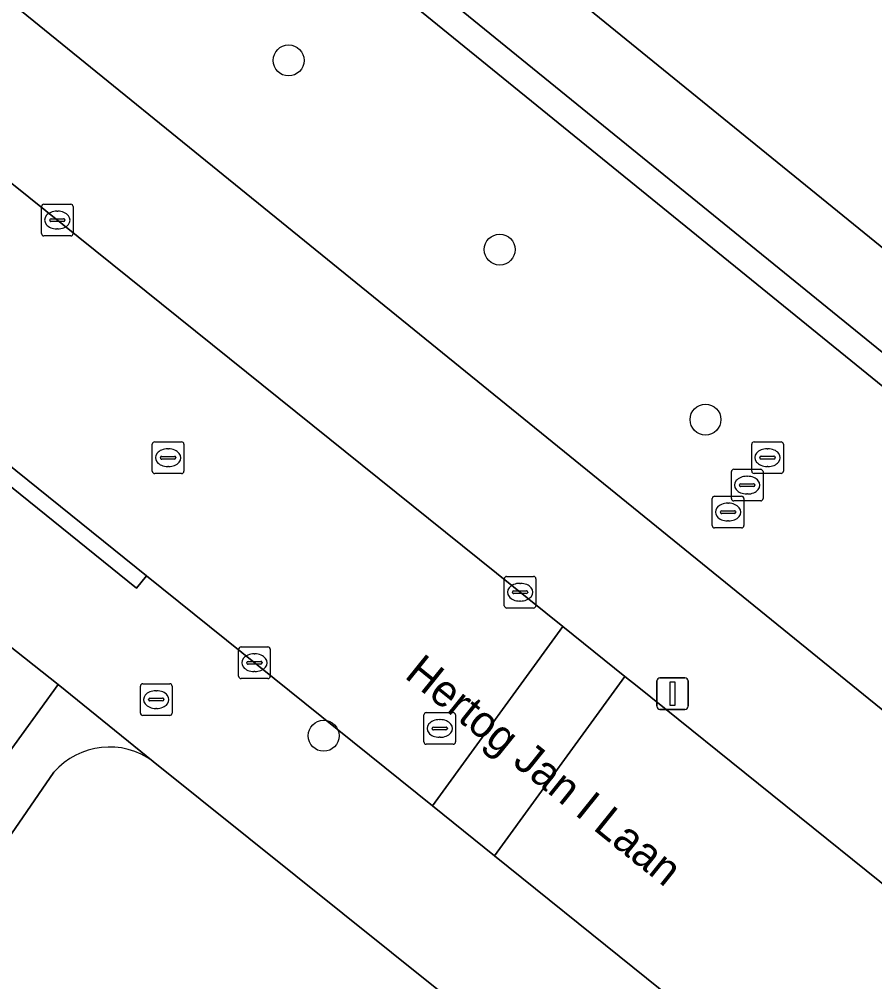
# Model space of a CAD drawing. Extents: x 159674 to 160531, y 382172 to 382904.
# Drawn here: x 160312.02 to 160339.08, y 382680.52 to 382710.95 of the extents above; entities that cross this region are included whole.
import ezdxf

# ---------------------------------------------------------------- set-up
doc = ezdxf.new("R2010")
doc.units = 0
for name, color, linetype in [('IMGEO_Boom', 7, 'Continuous'), ('IMGEO_Brandkraan', 7, 'Continuous'), ('IMGEO_Erf', 7, 'Continuous'), ('IMGEO_Groenvoorziening', 7, 'Continuous'), ('IMGEO_Haag', 7, 'Continuous'), ('IMGEO_Kolk', 7, 'Continuous'), ('IMGEO_Lichtmast', 7, 'Continuous'), ('IMGEO_Openbare_ruimte_label', 7, 'Continuous'), ('IMGEO_Pand', 7, 'Continuous'), ('IMGEO_Rijbaan_lokaal_open', 7, 'Continuous'), ('IMGEO_Rioolput', 7, 'Continuous'), ('IMGEO_Voetpad_open', 7, 'Continuous')]:
    doc.layers.add(name, color=color, linetype=linetype)

msp = doc.modelspace()

# ---------------------------------------------------------------- linework, layer by layer
at = {"layer": 'IMGEO_Boom'}
for centre in [(160320.54, 382709.645), (160327.217, 382703.665), (160333.725, 382698.29), (160321.648, 382688.295)]:
    msp.add_circle(centre, 0.489, dxfattribs=at)
at = {"layer": 'IMGEO_Brandkraan'}
for p, q in [((160315.853, 382689.013), (160315.853, 382689.865)), ((160315.928, 382689.939), (160316.78, 382689.939)), ((160316.341, 382689.719), (160316.366, 382689.719)), ((160316.854, 382689.865), (160316.854, 382689.013)), ((160316.112, 382689.433), (160316.112, 382689.445)), ((160316.155, 382689.482), (160316.553, 382689.482)), ((160316.596, 382689.445), (160316.596, 382689.433)), ((160316.55, 382689.396), (160316.152, 382689.396)), ((160316.364, 382689.159), (160316.339, 382689.159)), ((160316.78, 382688.939), (160315.928, 382688.939))]:
    msp.add_line(p, q, dxfattribs=at)
for points in [[(160315.853, 382689.013), (160315.853, 382689.865)], [(160315.928, 382689.939), (160316.78, 382689.939)], [(160316.854, 382689.865), (160316.854, 382689.013)], [(160316.78, 382688.939), (160315.928, 382688.939)]]:
    msp.add_lwpolyline(points, dxfattribs=at)
for centre, radius, start, end in [((160315.93, 382689.863), 0.0765, 91.552, 178.448), ((160315.93, 382689.863), 0.0765, 91.552, 178.448), ((160316.778, 382689.863), 0.0765, 1.552, 88.448), ((160316.778, 382689.863), 0.0765, 1.552, 88.448), ((160316.152, 382689.442), 0.0403, 85.8775, 175.7526), ((160316.149, 382689.432), 0.0366, 178.938, 274.7102), ((160316.553, 382689.439), 0.043, 264.8664, 352.4533), ((160316.557, 382689.444), 0.0386, 1.7309, 96.639), ((160315.93, 382689.015), 0.0765, 181.552, 268.448), ((160315.93, 382689.015), 0.0765, 181.552, 268.448), ((160316.778, 382689.015), 0.0765, 271.552, 358.448), ((160316.778, 382689.015), 0.0765, 271.552, 358.448)]:
    msp.add_arc(centre, radius, start, end, dxfattribs=at)
for centre, major_axis, ratio, start_param, end_param in [((160316.34, 382689.439), (-0.387, 0.002), 0.722429, 4.712389, 7.853982), ((160316.365, 382689.439), (-0.39, 0.002), 0.717154, 1.570796, 4.712389)]:
    msp.add_ellipse(centre, major_axis=major_axis, ratio=ratio, start_param=start_param, end_param=end_param, dxfattribs=at)
at = {"layer": 'IMGEO_Erf'}
for points in [[(160332.815, 382674.214), (160316.257, 382687.487)], [(160313.115, 382687.143), (160310.913, 382683.952), (160308.167, 382680.148), (160311.466, 382677.75), (160310.092, 382675.86), (160308.689, 382673.931), (160305.386, 382676.323), (160303.294, 382673.468), (160307.737, 382670.249), (160304.18, 382665.339), (160303.078, 382666.137), (160301.672, 382664.196), (160298.315, 382666.628), (160294.169, 382660.875)]]:
    msp.add_lwpolyline(points, dxfattribs=at)
msp.add_arc((160314.874, 382685.601), 2.339, 53.7429, 138.7534, dxfattribs=at)
at = {"layer": 'IMGEO_Groenvoorziening'}
msp.add_lwpolyline([(160284.89, 382733.272), (160346.941, 382682.927), (160357.009, 382674.758), (160362, 382680.937), (160317.229, 382717.291), (160317.757, 382717.941), (160311.605, 382722.938), (160333.51, 382750), (160355.476, 382777.138), (160357.031, 382776.089), (160357.342, 382775.837), (160360.793, 382780.087), (160357.866, 382782.856), (160305.531, 382750), (160285.03, 382737.24)], dxfattribs=at)
msp.add_lwpolyline([(160317.229, 382717.291), (160362, 382680.937), (160377.094, 382699.627), (160376.864, 382699.817), (160375.385, 382701.033), (160360.708, 382683.056), (160317.757, 382717.941)], close=True, dxfattribs=at)
at = {"layer": 'IMGEO_Haag'}
msp.add_lwpolyline([(160317.229, 382717.291), (160362, 382680.937), (160377.094, 382699.627), (160376.864, 382699.817), (160375.385, 382701.033), (160360.708, 382683.056), (160317.757, 382717.941)], close=True, dxfattribs=at)
at = {"layer": 'IMGEO_Kolk'}
for p, q in [((160312.724, 382704.172), (160312.724, 382705.024)), ((160312.799, 382705.098), (160313.651, 382705.098)), ((160313.725, 382705.024), (160313.725, 382704.172)), ((160313.026, 382704.641), (160313.424, 382704.641)), ((160313.212, 382704.878), (160313.237, 382704.878)), ((160312.983, 382704.592), (160312.983, 382704.604)), ((160313.421, 382704.555), (160313.023, 382704.555)), ((160313.235, 382704.318), (160313.21, 382704.318)), ((160313.467, 382704.604), (160313.467, 382704.592)), ((160313.651, 382704.098), (160312.799, 382704.098)), ((160327.361, 382692.408), (160327.361, 382693.26)), ((160327.436, 382693.334), (160328.288, 382693.334)), ((160327.849, 382693.114), (160327.874, 382693.114)), ((160328.362, 382693.26), (160328.362, 382692.408)), ((160327.62, 382692.828), (160327.62, 382692.84)), ((160328.058, 382692.791), (160327.66, 382692.791)), ((160327.663, 382692.877), (160328.061, 382692.877)), ((160328.104, 382692.84), (160328.104, 382692.828)), ((160327.872, 382692.554), (160327.847, 382692.554)), ((160328.288, 382692.334), (160327.436, 382692.334)), ((160318.959, 382690.178), (160318.959, 382691.03)), ((160319.034, 382691.104), (160319.886, 382691.104)), ((160319.96, 382691.03), (160319.96, 382690.178)), ((160319.261, 382690.647), (160319.659, 382690.647)), ((160319.447, 382690.884), (160319.472, 382690.884)), ((160319.218, 382690.598), (160319.218, 382690.61)), ((160319.656, 382690.561), (160319.258, 382690.561)), ((160319.47, 382690.324), (160319.445, 382690.324)), ((160319.702, 382690.61), (160319.702, 382690.598)), ((160319.886, 382690.104), (160319.034, 382690.104))]:
    msp.add_line(p, q, dxfattribs=at)
for points in [[(160312.724, 382704.172), (160312.724, 382705.024)], [(160312.799, 382705.098), (160313.651, 382705.098)], [(160313.725, 382705.024), (160313.725, 382704.172)], [(160313.651, 382704.098), (160312.799, 382704.098)], [(160327.361, 382692.408), (160327.361, 382693.26)], [(160327.436, 382693.334), (160328.288, 382693.334)], [(160328.362, 382693.26), (160328.362, 382692.408)], [(160328.288, 382692.334), (160327.436, 382692.334)], [(160318.959, 382690.178), (160318.959, 382691.03)], [(160319.034, 382691.104), (160319.886, 382691.104)], [(160319.96, 382691.03), (160319.96, 382690.178)], [(160319.886, 382690.104), (160319.034, 382690.104)]]:
    msp.add_lwpolyline(points, dxfattribs=at)
for centre, radius, start, end in [((160312.801, 382705.022), 0.0765, 91.552, 178.448), ((160312.801, 382705.022), 0.0765, 91.552, 178.448), ((160313.649, 382705.022), 0.0765, 1.552, 88.448), ((160313.649, 382705.022), 0.0765, 1.552, 88.448), ((160313.023, 382704.601), 0.0403, 85.8775, 175.7526), ((160313.428, 382704.603), 0.0386, 1.7309, 96.639), ((160313.02, 382704.591), 0.0366, 178.938, 274.7102), ((160313.424, 382704.598), 0.043, 264.8664, 352.4533), ((160312.801, 382704.174), 0.0765, 181.552, 268.448), ((160312.801, 382704.174), 0.0765, 181.552, 268.448), ((160313.649, 382704.174), 0.0765, 271.552, 358.448), ((160313.649, 382704.174), 0.0765, 271.552, 358.448), ((160327.438, 382693.258), 0.0765, 91.552, 178.448), ((160327.438, 382693.258), 0.0765, 91.552, 178.448), ((160328.286, 382693.258), 0.0765, 1.552, 88.448), ((160328.286, 382693.258), 0.0765, 1.552, 88.448), ((160327.66, 382692.837), 0.0403, 85.8775, 175.7526), ((160327.657, 382692.827), 0.0366, 178.938, 274.7102), ((160328.061, 382692.834), 0.043, 264.8664, 352.4533), ((160328.065, 382692.839), 0.0386, 1.7309, 96.639), ((160327.438, 382692.41), 0.0765, 181.552, 268.448), ((160327.438, 382692.41), 0.0765, 181.552, 268.448), ((160328.286, 382692.41), 0.0765, 271.552, 358.448), ((160328.286, 382692.41), 0.0765, 271.552, 358.448), ((160319.036, 382691.028), 0.0765, 91.552, 178.448), ((160319.036, 382691.028), 0.0765, 91.552, 178.448), ((160319.884, 382691.028), 0.0765, 1.552, 88.448), ((160319.884, 382691.028), 0.0765, 1.552, 88.448), ((160319.258, 382690.607), 0.0403, 85.8775, 175.7526), ((160319.663, 382690.609), 0.0386, 1.7309, 96.639), ((160319.255, 382690.597), 0.0366, 178.938, 274.7102), ((160319.659, 382690.604), 0.043, 264.8664, 352.4533), ((160319.036, 382690.18), 0.0765, 181.552, 268.448), ((160319.036, 382690.18), 0.0765, 181.552, 268.448), ((160319.884, 382690.18), 0.0765, 271.552, 358.448), ((160319.884, 382690.18), 0.0765, 271.552, 358.448)]:
    msp.add_arc(centre, radius, start, end, dxfattribs=at)
for centre, major_axis, ratio, start_param, end_param in [((160313.211, 382704.598), (-0.387, 0.002), 0.722429, 4.712389, 7.853982), ((160313.236, 382704.598), (-0.39, 0.002), 0.717154, 1.570796, 4.712389), ((160327.848, 382692.834), (-0.387, 0.002), 0.722429, 4.712389, 7.853982), ((160327.873, 382692.834), (-0.39, 0.002), 0.717154, 1.570796, 4.712389), ((160319.446, 382690.604), (-0.387, 0.002), 0.722429, 4.712389, 7.853982), ((160319.471, 382690.604), (-0.39, 0.002), 0.717154, 1.570796, 4.712389)]:
    msp.add_ellipse(centre, major_axis=major_axis, ratio=ratio, start_param=start_param, end_param=end_param, dxfattribs=at)
at = {"layer": 'IMGEO_Lichtmast'}
for p, q in [((160332.184, 382689.228), (160332.184, 382690.028)), ((160332.184, 382690.028), (160332.184, 382689.228)), ((160332.284, 382690.128), (160333.074, 382690.128)), ((160333.074, 382690.128), (160332.284, 382690.128)), ((160333.174, 382690.028), (160333.174, 382689.228)), ((160333.174, 382689.228), (160333.174, 382690.028)), ((160333.074, 382689.128), (160332.284, 382689.128)), ((160332.284, 382689.128), (160333.074, 382689.128))]:
    msp.add_line(p, q, dxfattribs=at)
msp.add_lwpolyline([(160332.604, 382690.003), (160332.754, 382690.003), (160332.754, 382689.253), (160332.604, 382689.253), (160332.604, 382690.003)], dxfattribs=at)
for centre, start, end in [((160332.284, 382690.028), 90, 180), ((160332.284, 382690.028), 90, 180), ((160333.074, 382690.028), 0, 90), ((160333.074, 382690.028), 360, 90), ((160332.284, 382689.228), 180, 270), ((160332.284, 382689.228), 180, 270), ((160333.074, 382689.228), 270, 0), ((160333.074, 382689.228), 270, 0)]:
    msp.add_arc(centre, 0.1, start, end, dxfattribs=at)
at = {"layer": 'IMGEO_Pand'}
msp.add_lwpolyline([(160360.202, 382686.777), (160373.514, 382703.17), (160373.99, 382702.783), (160379.13, 382709.111), (160381.203, 382707.428), (160385.383, 382712.576), (160383.354, 382714.223), (160388.465, 382720.517), (160387.964, 382720.924), (160401.236, 382737.269), (160363.137, 382768.208), (160322.118, 382717.701)], close=True, dxfattribs=at)
at = {"layer": 'IMGEO_Rijbaan_lokaal_open'}
for points in [[(160329.213, 382691.747), (160292.249, 382721.456), (160287.892, 382716), (160311.584, 382696.94), (160316.045, 382693.352), (160325.09, 382686.076)], [(160331.172, 382690.173), (160329.213, 382691.747), (160325.09, 382686.076), (160327.048, 382684.5)]]:
    msp.add_lwpolyline(points, close=True, dxfattribs=at)
for points in [[(160281.885, 382651.597), (160284.25, 382649.875), (160313.249, 382689.912), (160309.343, 382693.001), (160289.284, 382665.402)], [(160331.562, 382689.859), (160331.172, 382690.173), (160327.048, 382684.5), (160335.801, 382677.459)], [(160336.801, 382669.305), (160336.907, 382669.427), (160344.376, 382679.555), (160331.562, 382689.859)]]:
    msp.add_lwpolyline(points, dxfattribs=at)
at = {"layer": 'IMGEO_Rioolput'}
for p, q in [((160316.229, 382696.66), (160316.229, 382697.512)), ((160316.304, 382697.586), (160317.156, 382697.586)), ((160316.717, 382697.366), (160316.742, 382697.366)), ((160317.23, 382697.512), (160317.23, 382696.66)), ((160335.186, 382696.662), (160335.186, 382697.514)), ((160335.261, 382697.588), (160336.113, 382697.588)), ((160335.674, 382697.368), (160335.699, 382697.368)), ((160336.187, 382697.514), (160336.187, 382696.662)), ((160316.488, 382697.08), (160316.488, 382697.092)), ((160316.926, 382697.043), (160316.528, 382697.043)), ((160316.531, 382697.129), (160316.929, 382697.129)), ((160316.972, 382697.092), (160316.972, 382697.08)), ((160335.445, 382697.082), (160335.445, 382697.094)), ((160335.883, 382697.045), (160335.485, 382697.045)), ((160335.488, 382697.131), (160335.886, 382697.131)), ((160335.929, 382697.094), (160335.929, 382697.082)), ((160316.74, 382696.806), (160316.715, 382696.806)), ((160334.618, 382696.719), (160335.47, 382696.719)), ((160335.697, 382696.808), (160335.672, 382696.808)), ((160317.156, 382696.586), (160316.304, 382696.586)), ((160334.543, 382695.793), (160334.543, 382696.645)), ((160335.031, 382696.499), (160335.056, 382696.499)), ((160336.113, 382696.588), (160335.261, 382696.588)), ((160335.544, 382696.645), (160335.544, 382695.793)), ((160334.802, 382696.213), (160334.802, 382696.225)), ((160335.24, 382696.176), (160334.842, 382696.176)), ((160334.845, 382696.262), (160335.243, 382696.262)), ((160335.286, 382696.225), (160335.286, 382696.213)), ((160333.939, 382694.941), (160333.939, 382695.793)), ((160334.014, 382695.867), (160334.866, 382695.867)), ((160334.94, 382695.793), (160334.94, 382694.941)), ((160335.054, 382695.939), (160335.029, 382695.939)), ((160334.427, 382695.647), (160334.452, 382695.647)), ((160335.47, 382695.719), (160334.618, 382695.719)), ((160334.198, 382695.361), (160334.198, 382695.373)), ((160334.636, 382695.324), (160334.238, 382695.324)), ((160334.241, 382695.41), (160334.639, 382695.41)), ((160334.682, 382695.373), (160334.682, 382695.361)), ((160334.45, 382695.087), (160334.425, 382695.087)), ((160334.866, 382694.867), (160334.014, 382694.867)), ((160324.82, 382688.1), (160324.82, 382688.952)), ((160324.895, 382689.026), (160325.747, 382689.026)), ((160325.308, 382688.806), (160325.333, 382688.806)), ((160325.821, 382688.952), (160325.821, 382688.1)), ((160325.079, 382688.52), (160325.079, 382688.532)), ((160325.122, 382688.569), (160325.52, 382688.569)), ((160325.563, 382688.532), (160325.563, 382688.52)), ((160325.517, 382688.483), (160325.119, 382688.483)), ((160325.331, 382688.246), (160325.306, 382688.246)), ((160325.747, 382688.026), (160324.895, 382688.026))]:
    msp.add_line(p, q, dxfattribs=at)
for points in [[(160316.229, 382696.66), (160316.229, 382697.512)], [(160316.304, 382697.586), (160317.156, 382697.586)], [(160317.23, 382697.512), (160317.23, 382696.66)], [(160335.186, 382696.662), (160335.186, 382697.514)], [(160335.261, 382697.588), (160336.113, 382697.588)], [(160336.187, 382697.514), (160336.187, 382696.662)], [(160334.618, 382696.719), (160335.47, 382696.719)], [(160317.156, 382696.586), (160316.304, 382696.586)], [(160334.543, 382695.793), (160334.543, 382696.645)], [(160336.113, 382696.588), (160335.261, 382696.588)], [(160335.544, 382696.645), (160335.544, 382695.793)], [(160333.939, 382694.941), (160333.939, 382695.793)], [(160334.014, 382695.867), (160334.866, 382695.867)], [(160334.94, 382695.793), (160334.94, 382694.941)], [(160335.47, 382695.719), (160334.618, 382695.719)], [(160334.866, 382694.867), (160334.014, 382694.867)], [(160324.82, 382688.1), (160324.82, 382688.952)], [(160324.895, 382689.026), (160325.747, 382689.026)], [(160325.821, 382688.952), (160325.821, 382688.1)], [(160325.747, 382688.026), (160324.895, 382688.026)]]:
    msp.add_lwpolyline(points, dxfattribs=at)
for centre, radius, start, end in [((160316.306, 382697.51), 0.0765, 91.552, 178.448), ((160316.306, 382697.51), 0.0765, 91.552, 178.448), ((160317.154, 382697.51), 0.0765, 1.552, 88.448), ((160317.154, 382697.51), 0.0765, 1.552, 88.448), ((160335.263, 382697.512), 0.0765, 91.552, 178.448), ((160335.263, 382697.512), 0.0765, 91.552, 178.448), ((160336.111, 382697.512), 0.0765, 1.552, 88.448), ((160336.111, 382697.512), 0.0765, 1.552, 88.448), ((160316.528, 382697.089), 0.0403, 85.8775, 175.7526), ((160316.525, 382697.079), 0.0366, 178.938, 274.7102), ((160316.929, 382697.086), 0.043, 264.8664, 352.4533), ((160316.933, 382697.091), 0.0386, 1.7309, 96.639), ((160335.485, 382697.091), 0.0403, 85.8775, 175.7526), ((160335.482, 382697.081), 0.0366, 178.938, 274.7102), ((160335.886, 382697.088), 0.043, 264.8664, 352.4533), ((160335.89, 382697.093), 0.0386, 1.7309, 96.639), ((160334.62, 382696.643), 0.0765, 91.552, 178.448), ((160334.62, 382696.643), 0.0765, 91.552, 178.448), ((160335.468, 382696.643), 0.0765, 1.552, 88.448), ((160335.468, 382696.643), 0.0765, 1.552, 88.448), ((160316.306, 382696.662), 0.0765, 181.552, 268.448), ((160316.306, 382696.662), 0.0765, 181.552, 268.448), ((160317.154, 382696.662), 0.0765, 271.552, 358.448), ((160317.154, 382696.662), 0.0765, 271.552, 358.448), ((160335.263, 382696.664), 0.0765, 181.552, 268.448), ((160335.263, 382696.664), 0.0765, 181.552, 268.448), ((160336.111, 382696.664), 0.0765, 271.552, 358.448), ((160336.111, 382696.664), 0.0765, 271.552, 358.448), ((160334.842, 382696.222), 0.0403, 85.8775, 175.7526), ((160334.839, 382696.212), 0.0366, 178.938, 274.7102), ((160335.243, 382696.219), 0.043, 264.8664, 352.4533), ((160335.247, 382696.224), 0.0386, 1.7309, 96.639), ((160334.016, 382695.791), 0.0765, 91.552, 178.448), ((160334.016, 382695.791), 0.0765, 91.552, 178.448), ((160334.62, 382695.795), 0.0765, 181.552, 268.448), ((160334.62, 382695.795), 0.0765, 181.552, 268.448), ((160334.864, 382695.791), 0.0765, 1.552, 88.448), ((160334.864, 382695.791), 0.0765, 1.552, 88.448), ((160335.468, 382695.795), 0.0765, 271.552, 358.448), ((160335.468, 382695.795), 0.0765, 271.552, 358.448), ((160334.238, 382695.37), 0.0403, 85.8775, 175.7526), ((160334.235, 382695.36), 0.0366, 178.938, 274.7102), ((160334.639, 382695.367), 0.043, 264.8664, 352.4533), ((160334.643, 382695.372), 0.0386, 1.7309, 96.639), ((160334.016, 382694.943), 0.0765, 181.552, 268.448), ((160334.016, 382694.943), 0.0765, 181.552, 268.448), ((160334.864, 382694.943), 0.0765, 271.552, 358.448), ((160334.864, 382694.943), 0.0765, 271.552, 358.448), ((160324.897, 382688.95), 0.0765, 91.552, 178.448), ((160324.897, 382688.95), 0.0765, 91.552, 178.448), ((160325.745, 382688.95), 0.0765, 1.552, 88.448), ((160325.745, 382688.95), 0.0765, 1.552, 88.448), ((160325.119, 382688.529), 0.0403, 85.8775, 175.7526), ((160325.116, 382688.519), 0.0366, 178.938, 274.7102), ((160325.52, 382688.526), 0.043, 264.8664, 352.4533), ((160325.524, 382688.531), 0.0386, 1.7309, 96.639), ((160324.897, 382688.102), 0.0765, 181.552, 268.448), ((160324.897, 382688.102), 0.0765, 181.552, 268.448), ((160325.745, 382688.102), 0.0765, 271.552, 358.448), ((160325.745, 382688.102), 0.0765, 271.552, 358.448)]:
    msp.add_arc(centre, radius, start, end, dxfattribs=at)
for centre, major_axis, ratio, start_param, end_param in [((160316.716, 382697.086), (-0.387, 0.002), 0.722429, 4.712389, 7.853982), ((160316.741, 382697.086), (-0.39, 0.002), 0.717154, 1.570796, 4.712389), ((160335.673, 382697.088), (-0.387, 0.002), 0.722429, 4.712389, 7.853982), ((160335.698, 382697.088), (-0.39, 0.002), 0.717154, 1.570796, 4.712389), ((160335.03, 382696.219), (-0.387, 0.002), 0.722429, 4.712389, 7.853982), ((160335.055, 382696.219), (-0.39, 0.002), 0.717154, 1.570796, 4.712389), ((160334.426, 382695.367), (-0.387, 0.002), 0.722429, 4.712389, 7.853982), ((160334.451, 382695.367), (-0.39, 0.002), 0.717154, 1.570796, 4.712389), ((160325.307, 382688.526), (-0.387, 0.002), 0.722429, 4.712389, 7.853982), ((160325.332, 382688.526), (-0.39, 0.002), 0.717154, 1.570796, 4.712389)]:
    msp.add_ellipse(centre, major_axis=major_axis, ratio=ratio, start_param=start_param, end_param=end_param, dxfattribs=at)
at = {"layer": 'IMGEO_Voetpad_open'}
for points in [[(160391.679, 382718.147), (160390.343, 382719.214), (160404.841, 382737.313), (160389.088, 382750), (160361.7, 382772.057), (160343.79, 382750), (160317.757, 382717.941), (160360.708, 382683.056), (160375.385, 382701.033), (160376.864, 382699.817)], [(160360.202, 382686.777), (160322.118, 382717.701), (160363.137, 382768.208), (160401.236, 382737.269), (160387.964, 382720.924), (160388.465, 382720.517), (160383.354, 382714.223), (160385.383, 382712.576), (160381.203, 382707.428), (160379.13, 382709.111), (160373.99, 382702.783), (160373.514, 382703.17)], [(160316.045, 382693.352), (160311.584, 382696.94), (160311.272, 382696.55), (160315.733, 382692.962)]]:
    msp.add_lwpolyline(points, close=True, dxfattribs=at)
for points in [[(160346.941, 382682.927), (160284.89, 382733.272)], [(160282.47, 382729.315), (160289.879, 382723.36), (160292.249, 382721.456), (160329.213, 382691.747), (160331.172, 382690.173), (160331.562, 382689.859), (160344.376, 382679.555), (160359.84, 382667.121), (160360.67, 382668.154), (160361.649, 382667.367), (160363.734, 382669.962), (160363.603, 382670.069), (160359.987, 382672.384), (160357.009, 382674.758), (160346.941, 382682.927)], [(160271.573, 382729.019), (160267.481, 382726.359), (160267.842, 382726.279), (160288.011, 382710.171), (160289.223, 382709.204), (160306.664, 382695.275), (160309.343, 382693.001), (160313.249, 382689.912), (160316.257, 382687.487), (160332.815, 382674.214), (160337.911, 382673.579)], [(160335.801, 382677.459), (160327.048, 382684.5), (160325.09, 382686.076), (160316.045, 382693.352), (160315.733, 382692.962), (160311.272, 382696.55), (160311.584, 382696.94), (160287.892, 382716)], [(160316.257, 382687.487), (160313.249, 382689.912), (160284.25, 382649.875), (160281.308, 382645.833)], [(160294.169, 382660.875), (160298.315, 382666.628), (160299.696, 382668.535), (160301.17, 382670.569), (160303.294, 382673.468), (160305.386, 382676.323), (160306.736, 382678.18), (160308.167, 382680.148), (160310.913, 382683.952), (160313.115, 382687.143)]]:
    msp.add_lwpolyline(points, dxfattribs=at)
msp.add_arc((160314.874, 382685.601), 2.339, 53.7429, 138.7534, dxfattribs=at)

# ---------------------------------------------------------------- texts
at = {"layer": 'IMGEO_Openbare_ruimte_label'}
msp.add_text('Hertog Jan I Laan', height=1, rotation=321.1702, dxfattribs=at).set_placement((160324.172, 382690.154))

doc.saveas('drawing.dxf')
